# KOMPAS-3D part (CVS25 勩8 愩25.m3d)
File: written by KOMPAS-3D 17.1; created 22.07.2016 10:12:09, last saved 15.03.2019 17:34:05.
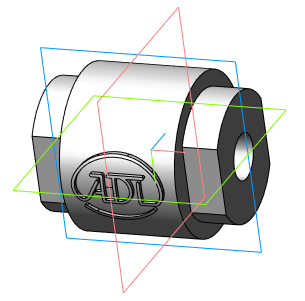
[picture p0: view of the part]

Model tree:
1. Операция без истории:2  (labels: Сталь 20  ГОСТ 1050-88)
